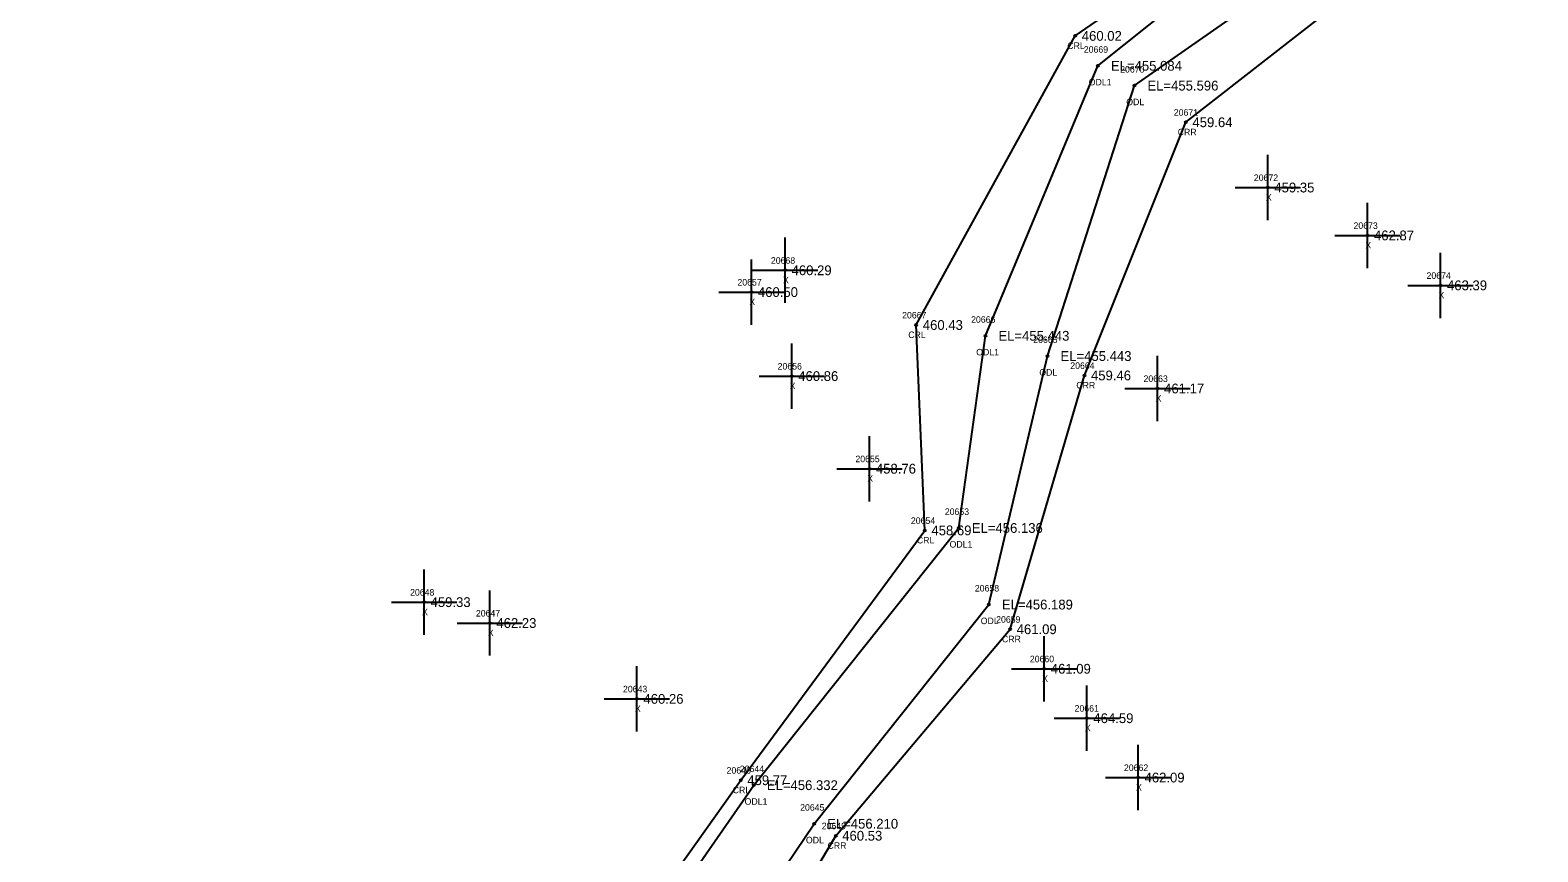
# Model space of a CAD drawing. Extents: x 1785066 to 1786589, y 770293 to 771312.
# Drawn here: x 1785796.9 to 1786028, y 771058.2 to 771184 of the extents above; entities that cross this region are included whole.
import ezdxf

# ---------------------------------------------------------------- set-up
doc = ezdxf.new("R2010")
doc.units = 0
for name, color, linetype in [('RD_EX_H2O', 7, 'Continuous'), ('RD_EX_H2O_txCode', 7, 'Continuous'), ('RD_EX_Misc', 7, 'Continuous'), ('RD_EX_Misc_txCode', 7, 'Continuous'), ('RD_EX_TX_H2O_ELEV', 7, 'Continuous'), ('RD_EX_TX_Misc_ELEV', 7, 'Continuous'), ('RD_SMD_Locator', 7, 'Continuous')]:
    doc.layers.add(name, color=color, linetype=linetype)

msp = doc.modelspace()

# ---------------------------------------------------------------- linework, layer by layer
at = {"layer": 'RD_EX_H2O'}
for points in [[(1785796.94, 770894.21), (1785817.52, 770934.08), (1785841.28, 770978.27), (1785905.84, 771069.13), (1785934.06, 771107.4), (1785932.74, 771138.87), (1785957.1, 771183.16), (1785993.97, 771208.54), (1785990.48, 771236.16), (1786004.55, 771296.27)], [(1785809.1, 770721.92), (1785797.13, 770787.08), (1785799.71, 770830.45), (1785797.84, 770854.32), (1785797.31, 770871.66), (1785799.74, 770882.87), (1785807.79, 770893.6), (1785824.76, 770932.46), (1785830, 770936.66), (1785845.12, 770978.01), (1785907.84, 771068.37), (1785939.25, 771107.77), (1785943.33, 771137.21), (1785960.57, 771178.58), (1785995.85, 771206.75), (1786007.06, 771230.75), (1786010.67, 771288.67)], [(1785820.66, 770730.64), (1785814.87, 770787.58), (1785810.48, 770814.19), (1785812.13, 770827.02), (1785814.82, 770830.33), (1785807.38, 770854.48), (1785804.49, 770870.81), (1785818.14, 770890.97), (1785834.56, 770929.05), (1785857.87, 770974.7), (1785917.08, 771062.46), (1785943.86, 771096.04), (1785952.84, 771134.11), (1785966.16, 771175.54), (1786004.33, 771202.23), (1786012.95, 771230.11), (1786017.56, 771287.45)], [(1785823.91, 770890.02), (1785840.03, 770925.86), (1785869.79, 770975.48), (1785920.39, 771060.62), (1785947.12, 771092.26), (1785958.51, 771131.14), (1785974.06, 771169.93), (1786009.64, 771197.71), (1786027.99, 771233.04), (1786021.73, 771286.51)]]:
    msp.add_lwpolyline(points, dxfattribs=at)
at = {"layer": 'RD_EX_Misc'}
for p, q in [((1785986.61, 771154.93), (1785986.61, 771164.93)), ((1785981.61, 771159.93), (1785991.61, 771159.93)), ((1786001.88, 771147.59), (1786001.88, 771157.59)), ((1785996.88, 771152.59), (1786006.88, 771152.59)), ((1785912.63, 771142.25), (1785912.63, 771152.25)), ((1785907.47, 771138.91), (1785907.47, 771148.91)), ((1786013.07, 771139.94), (1786013.07, 771149.94)), ((1785907.63, 771147.25), (1785917.63, 771147.25)), ((1785902.47, 771143.91), (1785912.47, 771143.91)), ((1786008.07, 771144.94), (1786018.07, 771144.94)), ((1785913.65, 771126.04), (1785913.65, 771136.04)), ((1785969.72, 771124.14), (1785969.72, 771134.14)), ((1785908.65, 771131.04), (1785918.65, 771131.04)), ((1785964.72, 771129.14), (1785974.72, 771129.14)), ((1785925.55, 771111.85), (1785925.55, 771121.85)), ((1785920.55, 771116.85), (1785930.55, 771116.85)), ((1785857.31, 771091.41), (1785857.31, 771101.41)), ((1785867.39, 771088.21), (1785867.39, 771098.21)), ((1785852.31, 771096.41), (1785862.31, 771096.41)), ((1785862.39, 771093.21), (1785872.39, 771093.21)), ((1785952.35, 771081.2), (1785952.35, 771091.2)), ((1785889.93, 771076.59), (1785889.93, 771086.59)), ((1785947.35, 771086.2), (1785957.35, 771086.2)), ((1785958.88, 771073.63), (1785958.88, 771083.63)), ((1785884.93, 771081.59), (1785894.93, 771081.59)), ((1785953.88, 771078.63), (1785963.88, 771078.63)), ((1785966.72, 771064.54), (1785966.72, 771074.54)), ((1785961.72, 771069.54), (1785971.72, 771069.54))]:
    msp.add_line(p, q, dxfattribs=at)
at = {"layer": 'RD_SMD_Locator'}
for centre in [(1785957.1, 771183.16), (1785960.57, 771178.58), (1785966.16, 771175.54), (1785974.06, 771169.93), (1785986.61, 771159.93), (1786001.88, 771152.59), (1785912.63, 771147.25), (1785907.47, 771143.91), (1786013.07, 771144.94), (1785932.74, 771138.87), (1785943.33, 771137.21), (1785952.84, 771134.11), (1785913.65, 771131.04), (1785958.51, 771131.14), (1785969.72, 771129.14), (1785925.55, 771116.85), (1785934.06, 771107.4), (1785939.25, 771107.77), (1785857.31, 771096.41), (1785943.86, 771096.04), (1785867.39, 771093.21), (1785947.12, 771092.26), (1785952.35, 771086.2), (1785889.93, 771081.59), (1785958.88, 771078.63), (1785966.72, 771069.54), (1785905.84, 771069.13), (1785907.84, 771068.37), (1785917.08, 771062.46), (1785920.39, 771060.62)]:
    msp.add_circle(centre, 0.15, dxfattribs=at)

# ---------------------------------------------------------------- texts
at = {"layer": 'RD_EX_H2O_txCode'}
for s, p in [('CRL', (1785955.88, 771181.16)), ('20669', (1785958.41, 771180.58)), ('20670', (1785963.98, 771177.54)), ('ODL1', (1785959.16, 771175.58)), ('ODL', (1785964.92, 771172.54)), ('20671', (1785972.2, 771170.93)), ('CRR', (1785972.8, 771167.93)), ('20667', (1785930.57, 771139.87)), ('20666', (1785941.14, 771139.21)), ('CRL', (1785931.51, 771136.87)), ('20665', (1785950.67, 771136.11)), ('ODL1', (1785941.92, 771134.21)), ('ODL', (1785951.59, 771131.11)), ('20664', (1785956.34, 771132.14)), ('CRR', (1785957.26, 771129.14)), ('20654', (1785931.91, 771108.4)), ('20653', (1785937.11, 771109.77)), ('CRL', (1785932.83, 771105.4)), ('ODL1', (1785937.84, 771104.77)), ('20658', (1785941.71, 771098.04)), ('ODL', (1785942.61, 771093.04)), ('20659', (1785944.98, 771093.26)), ('CRR', (1785945.87, 771090.26)), ('20646', (1785903.67, 771070.13)), ('20644', (1785905.7, 771070.37)), ('CRL', (1785904.61, 771067.13)), ('ODL1', (1785906.43, 771065.37)), ('20645', (1785914.94, 771064.46)), ('20649', (1785918.25, 771061.62)), ('ODL', (1785915.83, 771059.46)), ('CRR', (1785919.14, 771058.62))]:
    msp.add_text(s, height=1, dxfattribs=at).set_placement(p)
at = {"layer": 'RD_EX_Misc_txCode'}
for s, p in [('20672', (1785984.47, 771160.93)), ('X', (1785986.3, 771157.93)), ('20673', (1785999.74, 771153.59)), ('X', (1786001.56, 771150.59)), ('20668', (1785910.46, 771148.25)), ('20657', (1785905.33, 771144.91)), ('X', (1785912.31, 771145.25)), ('20674', (1786010.93, 771145.94)), ('X', (1786012.76, 771142.94)), ('X', (1785907.16, 771141.91)), ('20656', (1785911.49, 771132.04)), ('X', (1785913.34, 771129.04)), ('20663', (1785967.56, 771130.14)), ('X', (1785969.41, 771127.14)), ('20655', (1785923.41, 771117.85)), ('X', (1785925.23, 771114.85)), ('20648', (1785855.17, 771097.41)), ('X', (1785857, 771094.41)), ('20647', (1785865.25, 771094.21)), ('X', (1785867.08, 771091.21)), ('20660', (1785950.14, 771087.2)), ('20643', (1785887.79, 771082.59)), ('X', (1785952.03, 771084.2)), ('X', (1785889.62, 771079.59)), ('20661', (1785957, 771079.63)), ('X', (1785958.57, 771076.63)), ('20662', (1785964.56, 771070.54)), ('X', (1785966.41, 771067.54))]:
    msp.add_text(s, height=1, dxfattribs=at).set_placement(p)
at = {"layer": 'RD_EX_TX_H2O_ELEV'}
for s, p in [('460.02', (1785958.1, 771182.41)), ('EL=455.084', (1785962.57, 771177.83)), ('EL=455.596', (1785968.16, 771174.79)), ('459.64', (1785975.06, 771169.18)), ('460.43', (1785933.74, 771138.12)), ('EL=455.443', (1785945.33, 771136.46)), ('EL=455.443', (1785954.84, 771133.36)), ('459.46', (1785959.51, 771130.39)), ('458.69', (1785935.06, 771106.65)), ('EL=456.136', (1785941.25, 771107.02)), ('EL=456.189', (1785945.86, 771095.29)), ('461.09', (1785948.12, 771091.51)), ('459.77', (1785906.84, 771068.38)), ('EL=456.332', (1785909.84, 771067.62)), ('EL=456.210', (1785919.08, 771061.71)), ('460.53', (1785921.39, 771059.87))]:
    msp.add_text(s, height=1.5, dxfattribs=at).set_placement(p)
at = {"layer": 'RD_EX_TX_Misc_ELEV'}
for s, p in [('459.35', (1785987.61, 771159.18)), ('462.87', (1786002.88, 771151.84)), ('460.29', (1785913.63, 771146.5)), ('463.39', (1786014.07, 771144.19)), ('460.50', (1785908.47, 771143.16)), ('460.86', (1785914.65, 771130.29)), ('461.17', (1785970.72, 771128.39)), ('458.76', (1785926.55, 771116.1)), ('459.33', (1785858.31, 771095.66)), ('462.23', (1785868.39, 771092.46)), ('461.09', (1785953.35, 771085.45)), ('460.26', (1785890.93, 771080.84)), ('464.59', (1785959.88, 771077.88)), ('462.09', (1785967.72, 771068.79))]:
    msp.add_text(s, height=1.5, dxfattribs=at).set_placement(p)

doc.saveas('drawing.dxf')
